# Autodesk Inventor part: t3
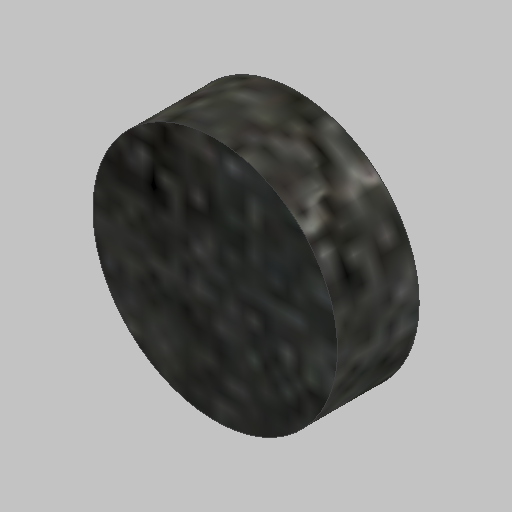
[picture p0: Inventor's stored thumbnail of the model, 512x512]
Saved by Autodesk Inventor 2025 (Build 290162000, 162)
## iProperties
Created: 2025-01
Part Number: t3
Material: Steel
Document SubType Name: Modeling
Designer: dansp
Mass: 6.93605 g
Surface Area: 5.89049 cm^2
Volume: 0.883573 cm^3
Density: 7.85 g/cm^3
Appearance: Plate
Author: dansp
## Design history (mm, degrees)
sketch "Sketch1"
  geometry: L1 (0, 10.5)-(0, -10.5) reference; L2 (-10.5, 0)-(10.5, 0) reference; C1 r 7.5 at (0, 0); 1 further point
  constraints: 1 centre point, 1 coincident
  dimensions: "d0" = 15 diameter of C1
extrude "Extrusion1" new body sketch "Sketch1" distance "d1" = 5; taper "d2" = 0 deg
body "Solid1"
